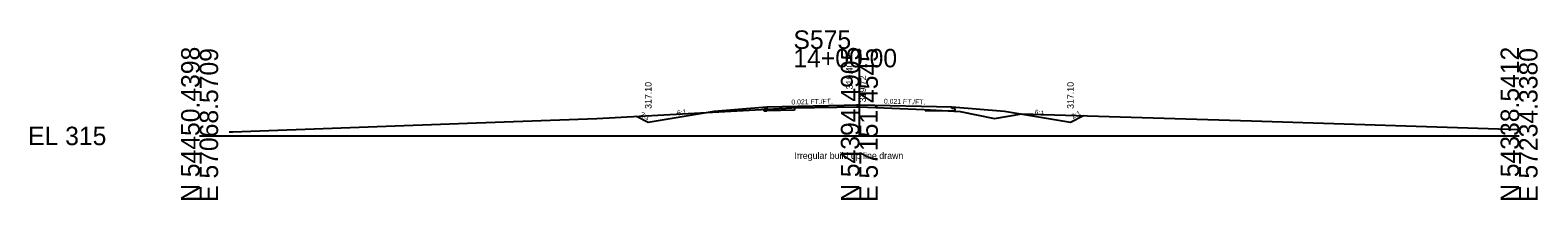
# Model space of a CAD drawing. Extents: x 10119 to 10347, y 94341 to 98867.
# Drawn here: x 10118.6 to 10347.2, y 97841.1 to 97866.8 of the extents above; entities that cross this region are included whole.
import ezdxf

# ---------------------------------------------------------------- set-up
doc = ezdxf.new("R2010")
doc.units = 0
for name, color, linetype in [('Level 10', 7, 'Continuous'), ('Level 11', 7, 'Continuous'), ('Level 12', 7, 'Continuous'), ('Level 32', 7, 'Continuous'), ('Level 33', 7, 'Continuous'), ('Level 50', 7, 'Continuous'), ('Level 59', 7, 'Continuous'), ('Level 6', 7, 'Continuous'), ('Level 60', 7, 'Continuous'), ('Level 63', 7, 'Continuous'), ('Level 7', 7, 'Continuous')]:
    doc.layers.add(name, color=color, linetype=linetype)

msp = doc.modelspace()

# ---------------------------------------------------------------- linework, layer by layer
at = {"layer": 'Level 11'}
for p, q in [((10230.31, 97854.95), (10229.81, 97854.94)), ((10229.81, 97854.94), (10229.81, 97854.6)), ((10229.81, 97854.6), (10230.31, 97854.61)), ((10230.31, 97855.24), (10230.31, 97854.95)), ((10258.31, 97854.95), (10258.31, 97855.24)), ((10258.81, 97854.94), (10258.31, 97854.95)), ((10258.31, 97854.61), (10258.81, 97854.6)), ((10258.81, 97854.6), (10258.81, 97854.94))]:
    msp.add_line(p, q, dxfattribs=at)
at = {"layer": 'Level 12'}
for p, q in [((10234.47, 97854.7), (10230.31, 97854.61)), ((10234.47, 97855.07), (10234.47, 97854.7)), ((10254.29, 97854.81), (10254.29, 97854.69)), ((10254.29, 97854.69), (10258.31, 97854.61))]:
    msp.add_line(p, q, dxfattribs=at)
at = {"layer": 'Level 59'}
for p, q in [((10230.31, 97855.24), (10244.31, 97855.53)), ((10244.31, 97855.53), (10258.31, 97855.24))]:
    msp.add_line(p, q, dxfattribs=at)
at = {"layer": 'Level 6'}
for p, q in [((10222.31, 97854.57), (10230.31, 97855.24)), ((10258.31, 97855.24), (10266.31, 97854.57))]:
    msp.add_line(p, q, dxfattribs=at)
at = {"layer": 'Level 60'}
for p, q in [((10186.26, 97852.79), (10204.52, 97853.47)), ((10204.52, 97853.47), (10234.08, 97855.06)), ((10234.08, 97855.06), (10244.31, 97855.21)), ((10244.31, 97855.21), (10254.11, 97854.82)), ((10254.11, 97854.82), (10259.6, 97854.49)), ((10259.6, 97854.49), (10264.82, 97853.46)), ((10264.82, 97853.46), (10268.96, 97854.18)), ((10268.96, 97854.18), (10303.74, 97853.08)), ((10148.79, 97851.43), (10149.36, 97851.43)), ((10149.36, 97851.43), (10186.26, 97852.79)), ((10303.74, 97853.08), (10344.31, 97851.79))]:
    msp.add_line(p, q, dxfattribs=at)
at = {"layer": 'Level 63'}
for p, q in [((10244.31, 97850.81), (10244.31, 97864.01)), ((10144.31, 97850.81), (10244.31, 97850.81)), ((10244.31, 97850.81), (10344.31, 97850.81))]:
    msp.add_line(p, q, dxfattribs=at)
at = {"layer": 'Level 7'}
for p, q in [((10210.54, 97853.8), (10212.31, 97852.91)), ((10212.31, 97852.91), (10222.31, 97854.57)), ((10266.31, 97854.57), (10276.31, 97852.91)), ((10276.31, 97852.91), (10278.27, 97853.89))]:
    msp.add_line(p, q, dxfattribs=at)

# ---------------------------------------------------------------- texts
at = {"layer": 'Level 10'}
msp.add_text('319.40', height=1, rotation=90, dxfattribs=at).set_placement((10243.31, 97857.86))
at = {"layer": 'Level 32'}
for s, rotation, p in [('0.021 FT./FT.', 1.1916, (10234.02, 97855.57)), ('0.021 FT./FT.', 358.8084, (10248.03, 97855.7)), ('2:1', 333.435, (10211.03, 97853.83)), ('6:1', 9.4623, (10216.75, 97853.9)), ('6:1', 350.5377, (10270.83, 97854.08)), ('2:1', 26.5651, (10276.68, 97853.37))]:
    msp.add_text(s, height=0.75, rotation=rotation, dxfattribs=at).set_placement(p)
at = {"layer": 'Level 33'}
for p in [(10212.81, 97854.91), (10276.81, 97854.91)]:
    msp.add_text('317.10', height=1, rotation=90, dxfattribs=at).set_placement(p)
at = {"layer": 'Level 50'}
msp.add_text('Irregular build up line drawn', height=1, dxfattribs=at).set_placement((10234.47, 97847.33))
at = {"layer": 'Level 59'}
msp.add_text(' 319.72', height=1, rotation=90, dxfattribs=at).set_placement((10245.31, 97855.53))
at = {"layer": 'Level 63'}
for s, p in [('S575', (10234.32, 97864.01)), ('14+00.00', (10234.31, 97861.21)), ('EL 315', (10118.31, 97849.41))]:
    msp.add_text(s, height=2.8, dxfattribs=at).set_placement(p)
for s, p in [('N 54450.4398', (10144.31, 97840.81)), ('E 57068.5709', (10147.11, 97840.81)), ('N 54394.4905', (10244.31, 97840.81)), ('E 57151.4545', (10247.11, 97840.81)), ('N 54338.5412', (10344.31, 97840.81)), ('E 57234.3380', (10347.11, 97840.81))]:
    msp.add_text(s, height=2.8, rotation=90, dxfattribs=at).set_placement(p)

doc.saveas('drawing.dxf')
